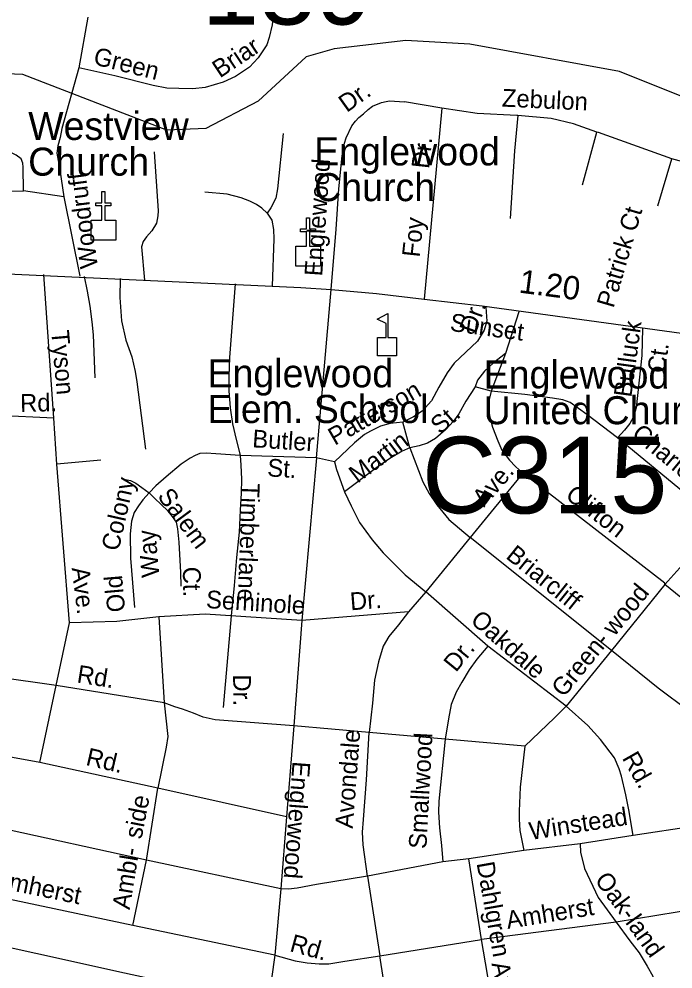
# Model space of a CAD drawing. Extents: x 2220236 to 2384410, y 720751 to 894131.
# Drawn here: x 2341238 to 2344734, y 803880 to 808960 of the extents above; entities that cross this region are included whole.
import ezdxf

# ---------------------------------------------------------------- set-up
doc = ezdxf.new("R2010")
doc.units = 0
doc.layers.add('Default', color=7, linetype='Continuous')

msp = doc.modelspace()

# ---------------------------------------------------------------- linework, layer by layer
at = {"layer": 'Default'}
for p, q in [((2341606.6, 808969.1), (2341557.9, 808698.6)), ((2343497.7, 808482.1), (2343298.9, 808517.5)), ((2343497.7, 808482.1), (2343404.6, 807462.1)), ((2344250, 808072.6), (2344327.4, 808354.9)), ((2344652, 807961.3), (2344727.2, 808211.2)), ((2341478.2, 808007.9), (2341261.7, 808041.3)), ((2341478.2, 808007.9), (2341563.2, 807584.1)), ((2341424.4, 806825.8), (2341371.6, 807592.9)), ((2342828.5, 806612.6), (2342907, 807512.4)), ((2343909.7, 807394.3), (2343839.4, 807170.7)), ((2343839.4, 807170.7), (2343761.9, 806969.9)), ((2343761.9, 806969.9), (2343675.6, 806992.8)), ((2341424.4, 806825.8), (2341098.3, 806839.9)), ((2341441.4, 806580), (2341424.4, 806825.8)), ((2343327.7, 806666.6), (2343290.1, 806804.1)), ((2344985.9, 806266.7), (2344436.6, 806720.1)), ((2342828.5, 806612.6), (2342420.5, 806626.3)), ((2342828.5, 806612.6), (2342750.9, 805744.1)), ((2342924.8, 806592), (2342828.5, 806612.6)), ((2341675.1, 806600.8), (2341441.4, 806580)), ((2341507.5, 805731.2), (2341441.4, 806580)), ((2343931.1, 806532), (2343649.4, 806186.8)), ((2344985.9, 806266.7), (2344689.9, 805935.3)), ((2343649.4, 806186.8), (2343413, 805896)), ((2344404.4, 805582.1), (2343649.4, 806186.8)), ((2344689.9, 805935.3), (2344404.4, 805582.1)), ((2343413, 805896), (2343320.3, 805789)), ((2343744.4, 805606), (2343413, 805896)), ((2341985, 805762.9), (2342014.6, 805303.5)), ((2343320.3, 805789), (2342750.9, 805744.1)), ((2341437.5, 805396.4), (2341507.5, 805731.2)), ((2342750.9, 805744.1), (2342707.7, 805179.7)), ((2344162, 805285.3), (2343744.4, 805606)), ((2344404.4, 805582.1), (2344162, 805285.3)), ((2341437.5, 805396.4), (2340676.4, 805503.1)), ((2341349.6, 804984.6), (2341437.5, 805396.4)), ((2342014.6, 805303.5), (2341437.5, 805396.4)), ((2342707.7, 805179.7), (2342668.4, 804693.6)), ((2343110.1, 805144.5), (2342707.7, 805179.7)), ((2343516.3, 805109.5), (2343110.1, 805144.5)), ((2343942.7, 805070.7), (2343516.3, 805109.5)), ((2341980, 804847.1), (2341349.6, 804984.6)), ((2341920.1, 804461.7), (2341980, 804847.1)), ((2342668.4, 804693.6), (2341980, 804847.1)), ((2341920.1, 804461.7), (2340746, 804720.3)), ((2342668.4, 804693.6), (2342638.4, 804307.7)), ((2345229.3, 804702), (2344521.6, 804593.5)), ((2344521.6, 804593.5), (2344236.9, 804548.5)), ((2344236.9, 804548.5), (2343937.4, 804512.8)), ((2343937.4, 804512.8), (2343641.9, 804469.1)), ((2341847.4, 804111.7), (2341920.1, 804461.7)), ((2342638.4, 804307.7), (2341920.1, 804461.7)), ((2343504.3, 804453.5), (2343101.1, 804377)), ((2343641.9, 804469.1), (2343504.3, 804453.5)), ((2343711.1, 804038.2), (2343641.9, 804469.1)), ((2343101.1, 804377), (2343167.8, 803950.8)), ((2341847.4, 804111.7), (2340779.2, 804338.5)), ((2342638.4, 804307.7), (2342605.9, 803953.4)), ((2344429.2, 804129.5), (2343711.1, 804038.2)), ((2342605.9, 803953.4), (2341847.4, 804111.7)), ((2343167.8, 803950.8), (2343711.1, 804038.2))]:
    msp.add_line(p, q, dxfattribs=at)
for points in [[(2342594.9, 809081.1), (2342599.8, 809009.1), (2342590.7, 808929.1), (2342575.5, 808860.8), (2342562.1, 808820.7), (2342516.9, 808752.2), (2342469.5, 808701.6), (2342396.1, 808652.8), (2342330.5, 808621.9), (2342232.9, 808592.9), (2342166.9, 808586), (2342093, 808587.2), (2342029.1, 808590.4), (2341954.9, 808603.6), (2341750.3, 808655.1), (2341557.9, 808698.6)], [(2345461.4, 808273.2), (2344448.4, 808678.2), (2343647.5, 808825.9), (2343305.4, 808844.8), (2342922.4, 808799.6), (2342773.3, 808757.5), (2342517.4, 808520.6), (2342236.3, 808374.5), (2342028.4, 808366), (2341258.4, 808662.7), (2340941.4, 808676)], [(2341557.9, 808698.6), (2341467.9, 808373.8), (2341458.4, 808325.6), (2341446.8, 808281.5), (2341441.5, 808241.5), (2341456.4, 808153.7), (2341478.2, 808007.9)], [(2342907, 807512.4), (2342933.8, 807835.5), (2342947.5, 808051.2), (2342966.3, 808227.5), (2342977.7, 808295.1), (2342986.6, 808324.7), (2343017.6, 808388.3), (2343036.5, 808414), (2343055.3, 808432.8), (2343079.2, 808453.4), (2343104.9, 808475.6), (2343126.9, 808493.3), (2343175.5, 808512.3), (2343200.6, 808518), (2343218.8, 808521.2), (2343298.9, 808517.5)], [(2343903.6, 808442.9), (2343898.5, 808443.1), (2343686.4, 808455.1), (2343497.7, 808482.1)], [(2343903.6, 808442.9), (2343886.5, 808254.8), (2343864.3, 807893.7)], [(2344327.4, 808354.9), (2344202.6, 808398.7), (2344082.4, 808426.9), (2343903.6, 808442.9)], [(2342649.6, 808348.1), (2342619.3, 808051.7), (2342611.9, 808001.6), (2342584.5, 807949.2), (2342564.8, 807921)], [(2344727.2, 808211.2), (2344335.2, 808352.2), (2344327.4, 808354.9)], [(2341261.7, 808041.3), (2341260.4, 808167.3), (2341258.1, 808189.2), (2341249.8, 808211.3), (2341223.6, 808230.8), (2341054.6, 808312.7), (2341018.7, 808304.3), (2341005.1, 808280.1), (2341003.6, 808238.2), (2341007.4, 808092.3), (2341013.7, 808064.4), (2341032, 808042.7), (2341064, 808037), (2341261.7, 808041.3)], [(2341961.1, 808249.7), (2341982.8, 807934.1), (2341981.3, 807908), (2341973.7, 807868.1), (2341948.2, 807827.6), (2341920.7, 807795.5), (2341902.9, 807769.1), (2341893.3, 807741.1), (2341908.8, 807564)], [(2345000.3, 807248.4), (2345046.2, 807667.8), (2345110.4, 808061.8), (2345110, 808079.6), (2345101.8, 808105.6), (2345089.5, 808121.3), (2344975.2, 808144.5), (2344727.2, 808211.2)], [(2342564.8, 807921), (2342536.5, 807948.7), (2342508.3, 807968.3), (2342472.1, 807985.9), (2342426, 808003.4), (2342351.8, 808022.6), (2342231.7, 808033.1)], [(2342564.8, 807921), (2342589.4, 807883.4), (2342598, 807833.5), (2342600.4, 807783.6), (2342591.7, 807531.3)], [(2340486.7, 807629.8), (2342745, 807523.7), (2342907, 807512.4), (2343149.5, 807491.1), (2343404.6, 807462.1), (2343714.1, 807426.7), (2345129.8, 807232.1), (2345977.7, 807154.8)], [(2341587.1, 807582.8), (2341602.2, 807503.6), (2341617.1, 807423.9), (2341628.1, 807339.9), (2341635, 807270.2), (2341643.7, 807040.3)], [(2341778.7, 807572.8), (2341776.5, 807469.9), (2341785.9, 807346), (2341809.2, 807242.3), (2341842.2, 807152.6), (2341859.2, 807074.9), (2341867.9, 807019), (2341915.3, 806659.8)], [(2342393, 807543), (2342383.1, 807405.3), (2342363.5, 807149.6), (2342359.6, 807047.3), (2342359.6, 806970.6), (2342367.4, 806880.1), (2342379.2, 806795.5), (2342398.9, 806710.9), (2342412.6, 806655.8), (2342420.5, 806626.3)], [(2343733.8, 807418.1), (2343739.5, 807344), (2343724, 807295.3), (2343688.8, 807236.8), (2343564.1, 807119.5), (2343526.9, 807066.9), (2343481.8, 806990.4), (2343442.7, 806918), (2343393.3, 806863.4), (2343347.7, 806832.9), (2343290.1, 806804.1)], [(2344570.6, 807305), (2344566.4, 807160.3), (2344536.7, 806881.3), (2344521.4, 806829), (2344503.7, 806796.9), (2344474.2, 806760.5), (2344436.6, 806720.1)], [(2343839.4, 807170.7), (2343772, 807119.9), (2343726.5, 807077.3), (2343689.3, 807028.9), (2343675.6, 806992.8)], [(2343675.6, 806992.8), (2343626.7, 806916.1), (2343589.4, 806847.8), (2343559.8, 806809.4), (2343518.5, 806763.1), (2343464.9, 806716.2), (2343421.3, 806691.9), (2343377.5, 806677.3), (2343327.7, 806666.6)], [(2343761.9, 806969.9), (2343746.6, 806903.6), (2343753.5, 806837.7), (2343768.2, 806778), (2343797, 806704.4), (2343819.6, 806654.7), (2343860.2, 806601.1), (2343892.6, 806567.4), (2343931.1, 806532)], [(2344436.6, 806720.1), (2344273.3, 806844.1), (2344184.4, 806908.9), (2344144.4, 806922.5), (2344090.2, 806931.9), (2343942.1, 806952), (2343761.9, 806969.9)], [(2343290.1, 806804.1), (2343222.1, 806797.4), (2343170.3, 806782.9), (2343116.6, 806756), (2343084.9, 806737.7), (2343031.5, 806693.1), (2342924.8, 806592)], [(2343327.7, 806666.6), (2343285.8, 806648.1), (2343220.4, 806609.4), (2343151, 806560.6), (2342978.6, 806430.5)], [(2343327.7, 806666.6), (2343395.9, 806485.5), (2343430.5, 806421.9), (2343471.4, 806362.6), (2343536.2, 806283.4), (2343649.4, 806186.8)], [(2342420.5, 806626.3), (2342290.7, 806634.2), (2342239.6, 806638.1), (2342204.2, 806636.2), (2342180.7, 806626.3), (2342153.1, 806610.6), (2342105.9, 806579.1), (2342025.3, 806512.2), (2341970.3, 806463.1), (2341934.9, 806425.7)], [(2342420.5, 806626.3), (2342424.4, 806573.2), (2342428.4, 806498.5), (2342426.4, 806423.7), (2342420.5, 806333.2), (2342414.6, 806215.2), (2342400.8, 806079.5), (2342388.1, 805930.9), (2342372.3, 805767.7), (2342330.1, 805278.8)], [(2342924.8, 806592), (2342935.3, 806550), (2342978.6, 806430.5)], [(2344689.9, 805935.3), (2344690, 805943.3), (2343931.1, 806532)], [(2341808.1, 806497.5), (2341833.7, 806491.6), (2341863.2, 806477.8), (2341894.6, 806454.2), (2341934.9, 806425.7)], [(2341934.9, 806425.7), (2341900.5, 806389.3), (2341876.9, 806355.9), (2341853.3, 806320.4), (2341839.6, 806275.2), (2341831.7, 806206.3), (2341833.7, 806076.5), (2341855.3, 805812.9)], [(2342105, 805927), (2342103, 805999.8), (2342095.1, 806163.1), (2342087.3, 806233.9), (2342079.4, 806269.3), (2342059.7, 806298.8), (2342036.2, 806328.3), (2341996.8, 806365.7), (2341965.4, 806393.2), (2341934.9, 806425.7)], [(2342978.6, 806430.5), (2343013.4, 806357.1), (2343058.5, 806267.7), (2343125.7, 806174.4), (2343184.6, 806105.2), (2343301.8, 805986.7), (2343413, 805896)], [(2331380.2, 806148.5), (2332089.7, 805986.2), (2332785.1, 805833.7), (2333023.7, 805785.1), (2333486.9, 805676.6), (2334090.2, 805538), (2335080.6, 805321.9), (2335954.5, 805132.5), (2336758.3, 804964.2), (2337494, 804803.2), (2338191.7, 804647.6), (2339171.9, 804437.5), (2339987.8, 804257.3), (2340853.6, 804069.8), (2341802, 803859.4), (2342517.6, 803703.9), (2343209.2, 803550.3), (2344249.4, 803324.9), (2344734.6, 803222.8), (2345460.4, 803059.6)], [(2345475.7, 805445), (2345395.5, 805463.9), (2345265, 805508.4), (2345156.3, 805559), (2345012.9, 805673.4), (2344689.9, 805935.3)], [(2341985, 805762.9), (2341761.3, 805738.1), (2341507.5, 805731.2)], [(2342750.9, 805744.1), (2342232.7, 805777.8), (2341985, 805762.9)], [(2343320.3, 805789), (2343267.1, 805720.4), (2343215.8, 805657.6), (2343184.5, 805605.3), (2343159.5, 805523.1), (2343138.7, 805424.8), (2343128.1, 805300.7), (2343110.1, 805144.5)], [(2343744.4, 805606), (2343685.1, 805537.3), (2343643.9, 805478.8), (2343604.7, 805414.4), (2343575.3, 805360.2), (2343548, 805293.8), (2343533.1, 805217.6), (2343516.3, 805109.5)], [(2345240.3, 805226.3), (2345178.6, 805203.6), (2345110.9, 805186.6), (2345045, 805177.9), (2344971, 805186.9), (2344884.6, 805220), (2344816.1, 805261), (2344654.7, 805381.1), (2344404.4, 805582.1)], [(2342014.6, 805303.5), (2342034.7, 805123.6), (2342025.3, 805065.6), (2341980, 804847.1)], [(2342707.7, 805179.7), (2342287.6, 805212.8), (2342223.4, 805226), (2342171.1, 805247.2), (2342112.8, 805268.5), (2342070.7, 805281.9), (2342014.6, 805303.5)], [(2344162, 805285.3), (2344100.7, 805222.6), (2343942.7, 805070.7)], [(2344521.6, 804593.5), (2344497.7, 804730.4), (2344482.3, 804810.9), (2344458.3, 804911.9), (2344446.4, 804949.5), (2344421.2, 805008.4), (2344346.1, 805107.5), (2344279.3, 805182.6), (2344162, 805285.3)], [(2343101.1, 804377), (2343077.2, 804544.3), (2343073.7, 804611.5), (2343078.9, 804679.9), (2343096, 804892.2), (2343110.1, 805144.5)], [(2341349.6, 804984.6), (2340848.5, 805075.3), (2340776.6, 805090.7), (2340713.3, 805102.7)], [(2343516.3, 805109.5), (2343482.3, 804777.1), (2343481, 804719.3), (2343486, 804635.2), (2343497.2, 804539.5), (2343504.3, 804453.5)], [(2343942.7, 805070.7), (2343917.2, 804852.3), (2343910.8, 804724.4), (2343911.4, 804680.4), (2343916, 804620.4), (2343937.4, 804512.8)], [(2344236.9, 804548.5), (2344239.3, 804504.3), (2344260.3, 804416.8), (2344334.2, 804261.7), (2344429.2, 804129.5)], [(2343101.1, 804377), (2342829.2, 804332.5), (2342724.8, 804312), (2342678.6, 804306.8), (2342638.4, 804307.7)], [(2345294.2, 804275.1), (2345081.8, 804237.7), (2344429.2, 804129.5)], [(2344429.2, 804129.5), (2344503, 804029.7), (2344553.8, 803966.3), (2344596.5, 803894.9), (2344625.1, 803841.2), (2344633.7, 803803.3), (2344642.4, 803741.5), (2344641.1, 803675.6), (2344637.8, 803619.4), (2344624.8, 803535.5)], [(2344624.8, 803535.5), (2344143.7, 803641.5), (2344077.7, 803644.8), (2343965.8, 803645.4), (2343852, 803636), (2343817.9, 803637.6), (2343791.8, 803645.3), (2343777.6, 803669.1), (2343764.9, 803715), (2343711.1, 804038.2)], [(2342605.9, 803953.4), (2342569.6, 803700.7), (2342518.1, 803429.1)], [(2342605.9, 803953.4), (2342713.7, 803924.3), (2342778.7, 803912.3), (2342843, 803907.9), (2342895, 803908.4), (2342980.7, 803921.5), (2343167.8, 803950.8)], [(2343163.5, 803280.6), (2343192.6, 803438.2), (2343207.5, 803512.4), (2343213, 803570.5), (2343210.2, 803632.4), (2343203.1, 803720.1), (2343167.8, 803950.8)]]:
    msp.add_lwpolyline(points, dxfattribs=at)
for points in [[(2341624.8, 807884), (2341681.8, 807884.1), (2341681.8, 807960.3), (2341649.8, 807960.3), (2341649.8, 807976.3), (2341681.8, 807976.3), (2341681.8, 808036.4), (2341697.8, 808036.4), (2341697.8, 807976.3), (2341729.8, 807976.3), (2341729.8, 807960.3), (2341697.8, 807960.3), (2341697.8, 807884.1), (2341755.4, 807884), (2341755.4, 807777.6), (2341624.8, 807777.6)], [(2342718.6, 807744.9), (2342775.6, 807745), (2342775.6, 807821.1), (2342743.6, 807821.1), (2342743.6, 807837.1), (2342775.6, 807837.1), (2342775.6, 807897.3), (2342791.6, 807897.3), (2342791.6, 807837.1), (2342823.6, 807837.1), (2342823.6, 807821.1), (2342791.6, 807821.1), (2342791.6, 807745), (2342849.2, 807744.9), (2342849.2, 807638.4), (2342718.6, 807638.4)], [(2343154.2, 807158.3), (2343154.2, 807256.2), (2343200.3, 807256.2), (2343200.3, 807331.3), (2343153.2, 807355.5), (2343209.9, 807384.7), (2343209.9, 807256.2), (2343255.9, 807256.2), (2343255.9, 807158.3)]]:
    msp.add_lwpolyline(points, close=True, dxfattribs=at)

# ---------------------------------------------------------------- texts
for s, height, p in [('189', 410.1, (2342215.5, 808930.2)), ('Westview', 150, (2341287.5, 808312.9)), ('Englewood', 150, (2342815.7, 808176.7)), ('Church', 150, (2341287.5, 808121.9)), ('Church', 150, (2342815.7, 807985.7)), ('Englewood', 150, (2342245.8, 806990.3)), ('Englewood', 150, (2343721.6, 806983.7)), ('Elem. School', 150, (2342245.8, 806799.3)), ('United Church', 150, (2343721.6, 806792.7)), ('C315', 410.1, (2343392.4, 806316))]:
    msp.add_text(s, height=height, dxfattribs=at).set_placement(p)
for s, height, rotation, p in [('Briar', 95, 33.6179, (2342312.1, 808641.7)), ('Green', 95, 345.8717, (2341630.6, 808718.8)), ('Dr.', 95, 35.5131, (2342990.2, 808456.8)), ('Zebulon', 95, 357.3338, (2343817.9, 808491.5)), ('Dr.', 95, 83.9074, (2343430, 808156.4)), ('Englewood', 95, 86.1244, (2342858.6, 807582.1)), ('Woodruff', 95, 97.4306, (2341660.5, 807631.9)), ('Patrick Ct', 95, 73.6597, (2344415.7, 807410.1)), ('Foy', 95, 83.9074, (2343379.4, 807682.9)), ('1.20', 125, 352.5393, (2343906.4, 807497.2)), ('Dr.', 95, 70.2828, (2343678.9, 807271.6)), ('Sunset', 95, 352.1346, (2343538, 807292.8)), ('Bulluck', 95, 82.2447, (2344510.7, 806933.7)), ('Tyson', 95, 275.0682, (2341410.5, 807291.3)), ('Ct.', 95, 82.2447, (2344690.3, 807062)), ('Patterson', 95, 29.994, (2342926.1, 806676.9)), ('Rd.', 95, 1.3558, (2341245.4, 806858.3)), ('St.', 95, 41.1882, (2343489.1, 806735.1)), ('Butler', 95, 356.279, (2342483.3, 806669.7)), ('Charlotte', 95, 320.4634, (2344507.3, 806729.6)), ('Martin', 95, 37.0403, (2343047.3, 806474)), ('St.', 95, 356.3622, (2342563.4, 806514.4)), ('Colony', 95, 77.3227, (2341770.4, 806110.3)), ('Ave.', 95, 48.9194, (2343723.9, 806346.1)), ('Timberlane', 95, 267.8405, (2342430.7, 806479.7)), ('Clifton', 95, 322.1984, (2344152.9, 806401.5)), ('Salem', 95, 306.5099, (2341974.8, 806407.4)), ('Way', 95, 95.1227, (2341989.4, 805978.5)), ('Briarcliff', 95, 321.3079, (2343835.5, 806079.8)), ('Ave.', 95, 276.8602, (2341520, 806024.2)), ('Ct.', 95, 270.8324, (2342114.2, 806030.3)), ('Old', 95, 95.0862, (2341806.2, 805791.9)), ('Seminole', 95, 356.279, (2342236.1, 805810.4)), ('wood', 95, 51.0506, (2344421.1, 805655)), ('Dr.', 95, 4.5089, (2343011.1, 805797.5)), ('Oakdale', 95, 318.8117, (2343645.7, 805735.9)), ('Green-', 95, 50.761, (2344149.5, 805328.2)), ('Dr.', 95, 50.7839, (2343573.4, 805462.6)), ('Rd.', 95, 350.8551, (2341544, 805412.5)), ('Dr.', 95, 270.6537, (2342382.6, 805454.4)), ('Avondale', 95, 85.5954, (2343022.1, 804628.8)), ('Smallwood', 95, 86.9519, (2343415.7, 804520.3)), ('Rd.', 95, 346.9164, (2341591, 804971.2)), ('Rd.', 95, 299.7033, (2344459.3, 805007.8)), ('Englewood', 95, 265.6013, (2342701.2, 804992.7)), ('side', 95, 79.045, (2341893.2, 804571.4)), ('Winstead', 95, 8.8834, (2343973, 804569.6)), ('Ambl-', 95, 80.792, (2341829.6, 804194.3)), ('Dahlgren', 95, 280.0473, (2343683.6, 804445.7)), ('Amherst', 95, 348.4123, (2341096.6, 804320.3)), ('Oak-', 95, 306.6925, (2344311.7, 804354.8)), ('Amherst', 95, 9.2247, (2343849.9, 804094)), ('land', 95, 305.4493, (2344476, 804128.3)), ('Rd.', 95, 344.7871, (2342680.7, 803976.2)), ('Ave.', 95, 281.5836, (2343763, 803909.5))]:
    msp.add_text(s, height=height, rotation=rotation, dxfattribs=at).set_placement(p)

doc.saveas('drawing.dxf')
